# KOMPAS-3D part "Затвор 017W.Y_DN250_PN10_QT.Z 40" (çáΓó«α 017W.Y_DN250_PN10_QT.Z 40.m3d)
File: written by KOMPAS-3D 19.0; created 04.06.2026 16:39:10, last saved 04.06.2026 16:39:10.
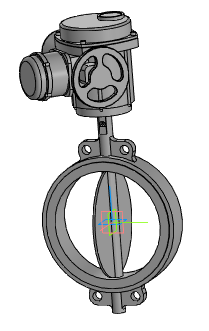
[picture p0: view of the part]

Document properties: Автор: Энергия; Полное имя файла: ..\..\..\3d для проектировщиков\017W разные\x.x Тип 017W.Y(S) Затвор дисковый поворотный межфланцевый\Затвор 017W.Y(S)_DN32-DN450_QT.Z\Затвор 017W.Y_DN250_PN10_QT.Z 40.a3d

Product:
- Part/product: Затвор 017W.Y_DN250_PN10_QT.Z 40
    Масса: 62.9462

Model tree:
1. Операция без истории:1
